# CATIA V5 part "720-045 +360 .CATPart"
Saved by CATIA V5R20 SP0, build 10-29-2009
Part number: 720-045 +360 
Revision: QUALSIASI
Definition: SCONOSCIUTO
Nomenclature: 720-045 +360 
Source: Unknown
Bounding box of the stored display mesh (mm): x -49.826 to 49.826, y -5 to 360, z -25.5 to 25.5
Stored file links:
  C:\Users\Utente\Desktop\IO LAVORO\3D X SITO CF\X 3D SITO CF 27-09-2020\720\720-045 +360 .CATPart
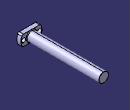
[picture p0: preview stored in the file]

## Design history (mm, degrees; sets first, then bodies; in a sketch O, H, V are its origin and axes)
Body1 "NONE" (main body)
  Solid1: solid without history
